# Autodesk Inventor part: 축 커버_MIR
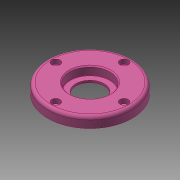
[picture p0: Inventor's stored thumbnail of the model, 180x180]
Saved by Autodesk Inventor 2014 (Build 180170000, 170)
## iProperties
Created: 2015-10
Part Number: 축 커버_MIR
Material: 강철, 연강
Document SubType Name: Modeling
Designer: kb542-02
Density: 7.86 g/cm^3
Appearance: 강철
Author: mdu
d0: 10.000 mm
d1: 0.00 deg
d2: 3.000 mm
d3: 0.00 deg
d6: 27.000 mm
d8: 38.000 mm
d9: 8.000 mm
d13: 40.000 mm
d14: 3.000 mm
d15: 0.00 deg
d16: 4.500 mm
d18: 8.000 mm
d19: 4.400 mm
d23: 4.000 ul
d24: 360.00 deg
d26: 3.000 mm
d27: 0.300 mm
d28: 1.000 mm
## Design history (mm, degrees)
derived "축 커버.ipt"
  sketch "스케치1"
    geometry: C1 r 40 at (0, 0) reference; C2 r 26 at (0, 0) reference; 1 further point
  sketch "스케치2"
    geometry: C1 r 20 at (0, 0) reference; 1 further point
  sketch "스케치3"
    geometry: C1 r 1.621 at (0, 32.5) reference; 1 further point
feature "솔리드1::축 커버.ipt"
tag "피쳐 태그1"
node "솔리드1"
other parameters: "d0" = 10, "d1" = 0 deg, "d2" = 3, "d3" = 0 deg, "d6" = 27, "d8" = 38, "d9" = 8, "d13" = 40, "d14" = 3, "d15" = 0 deg, "d16" = 4.5, "d18" = 8, "d19" = 4.4, "d23" = 4, "d24" = 360 deg, "d26" = 3, "d27" = 0.3, "d28" = 1
